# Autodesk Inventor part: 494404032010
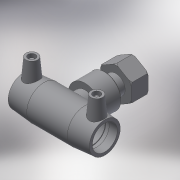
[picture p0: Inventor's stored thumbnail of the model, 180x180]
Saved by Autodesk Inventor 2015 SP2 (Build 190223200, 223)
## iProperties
Created: 2017-06
Part Number: 494404032010
Material: Generic
Description: PLASSON FREE NUT TRANSITION TEE 32-1"
Document SubType Name: Modeling
Designer: KIM
Mass: 128.46 g
Surface Area: 447.881 cm^2
Volume: 128.46 cm^3
Density: 1 g/cm^3
Appearance: Default
Author: KIM
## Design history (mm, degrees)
derived "494404.ipt"
feature "Solid1::494404.ipt"
tag "TaggingFeature1"
body "Solid1"
other parameters: "d0" = 104, "d1" = 32, "d2" = 44, "d3" = 39, "d4" = 26, "d5" = 39.6, "d6" = 30.4, "d7" = 32, "d8" = 168 deg, "d10" = 15.6, "d11" = 5.2, "d23" = 44, "d29" = 43, "d30" = 15, "d31" = 41.6, "d34" = 5 deg, "d40" = 9.6, "d41" = 4.8, "d42" = 6, "d43" = 0, "d84" = 3, "d85" = 0, "d91" = 88, "d93" = 30.291, "d94" = 27.2619, "d95" = 21.2037, "d96" = 18.1746, "d98" = 22, "d99" = 2.2, "d100" = 17.6, "d101" = 24.2328, "d102" = 24.2328, "d103" = 52.8, "d105" = 1.51455, "d109" = 0, "d111" = 42.4074, "d112" = 26.4, "d113" = 45.4365, "d114" = 242.4125, "d115" = 0, "d_" = 32, "L_" = 104, "L_1" = 39, "D_" = 44, "A_" = 43, "d_2" = 12, "H_" = 88, "G_" = 30.291
